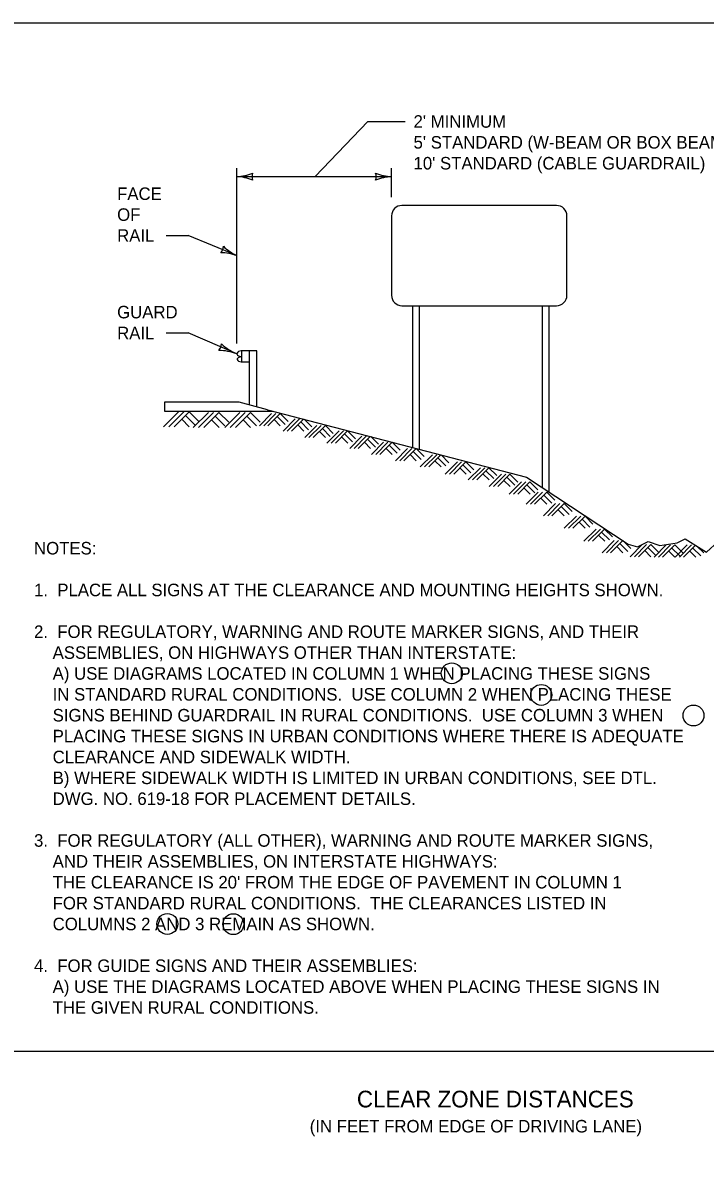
# Model space of a CAD drawing. Extents: x 49991.4 to 50021, y 49987.6 to 50011.4.
# Drawn here: x 50008.27 to 50011.54, y 49993.57 to 49999 of the extents above; entities that cross this region are included whole.
import ezdxf

# ---------------------------------------------------------------- set-up
doc = ezdxf.new("R2010")
doc.units = 0
for name, color, linetype in [('Level 1', 7, 'Continuous'), ('Level 2', 7, 'Continuous'), ('Level 3', 7, 'Continuous')]:
    doc.layers.add(name, color=color, linetype=linetype)

msp = doc.modelspace()

# ---------------------------------------------------------------- linework, layer by layer
at = {"layer": 'Level 1'}
for p, q in [((50010.8306, 49998.1235), (50010.0905, 49998.1235)), ((50010.0405, 49998.0735), (50010.0405, 49997.6934)), ((50010.8806, 49997.6934), (50010.8806, 49998.0735)), ((50010.0905, 49997.6434), (50010.8306, 49997.6434)), ((50010.1417, 49996.9646), (50010.1417, 49997.6434)), ((50010.1738, 49996.9562), (50010.1738, 49997.6434)), ((50010.7629, 49996.7725), (50010.7629, 49997.6434)), ((50010.795, 49996.7514), (50010.795, 49997.6434)), ((50009.3603, 49997.4275), (50009.3197, 49997.4275)), ((50009.3215, 49997.4275), (50009.3215, 49997.3742)), ((50009.3603, 49997.1675), (50009.3603, 49997.4275)), ((50009.3957, 49997.4275), (50009.3603, 49997.4275)), ((50009.3957, 49997.1586), (50009.3957, 49997.4275)), ((50009.3197, 49997.3742), (50009.3603, 49997.3742)), ((50008.9487, 49997.0636), (50009.0207, 49997.1356)), ((50009.31, 49997.1809), (50008.9538, 49997.1809)), ((50008.9538, 49997.1809), (50008.9538, 49997.1383)), ((50008.9538, 49997.1383), (50009.4739, 49997.1383)), ((50008.974, 49997.0636), (50009.046, 49997.1356)), ((50008.9991, 49997.0636), (50009.0711, 49997.1356)), ((50009.0711, 49997.1356), (50009.118, 49997.0888)), ((50009.0912, 49997.0606), (50009.1632, 49997.1326)), ((50009.1165, 49997.0606), (50009.1885, 49997.1326)), ((50009.1416, 49997.0606), (50009.2136, 49997.1326)), ((50009.2136, 49997.1326), (50009.2605, 49997.0858)), ((50009.2425, 49997.0606), (50009.3145, 49997.1326)), ((50009.2678, 49997.0606), (50009.3398, 49997.1326)), ((50009.2929, 49997.0606), (50009.3649, 49997.1326)), ((50009.446, 49997.1455), (50009.31, 49997.1809)), ((50009.3649, 49997.1326), (50009.4118, 49997.0858)), ((50009.446, 49997.1455), (50010.6864, 49996.8229)), ((50009.4737, 49997.1383), (50009.4737, 49997.1383)), ((50009.0355, 49997.0999), (50009.0719, 49997.0636)), ((50009.0534, 49997.1178), (50009.1002, 49997.0711)), ((50009.178, 49997.0969), (50009.2144, 49997.0606)), ((50009.1958, 49997.1148), (50009.2426, 49997.0681)), ((50009.3293, 49997.0969), (50009.3657, 49997.0606)), ((50009.3471, 49997.1148), (50009.3939, 49997.0681)), ((50009.4076, 49997.0684), (50009.4659, 49997.1267)), ((50009.4281, 49997.0684), (50009.4864, 49997.1267)), ((50009.4484, 49997.0684), (50009.5067, 49997.1267)), ((50009.4779, 49997.0979), (50009.5075, 49997.0684)), ((50009.4923, 49997.1124), (50009.5303, 49997.0745)), ((50009.5067, 49997.1267), (50009.5447, 49997.0888)), ((50009.5209, 49997.0431), (50009.5792, 49997.1014)), ((50009.5414, 49997.0431), (50009.5997, 49997.1014)), ((50009.5617, 49997.0431), (50009.6192, 49997.1005)), ((50009.6057, 49997.0871), (50009.6436, 49997.0492)), ((50009.6217, 49997.0998), (50009.658, 49997.0635)), ((50009.5912, 49997.0725), (50009.6208, 49997.0431)), ((50009.6246, 49997.0115), (50009.6829, 49997.0698)), ((50009.6451, 49997.0115), (50009.7034, 49997.0698)), ((50009.6654, 49997.0115), (50009.7237, 49997.0698)), ((50009.6949, 49997.041), (50009.7244, 49997.0115)), ((50009.7094, 49997.0555), (50009.7473, 49997.0176)), ((50009.7237, 49997.0698), (50009.7617, 49997.0319)), ((50009.731, 49996.9853), (50009.7893, 49997.0437)), ((50009.7516, 49996.9853), (50009.8099, 49997.0437)), ((50009.7719, 49996.9853), (50009.8302, 49997.0437)), ((50009.8158, 49997.0293), (50009.8537, 49996.9914)), ((50009.8302, 49997.0437), (50009.8682, 49997.0057)), ((50009.8014, 49997.0147), (50009.8309, 49996.9853)), ((50009.8405, 49996.9602), (50009.8988, 49997.0185)), ((50009.861, 49996.9602), (50009.9194, 49997.0185)), ((50009.8814, 49996.9602), (50009.9386, 49997.0174)), ((50009.9109, 49996.9896), (50009.9403, 49996.9602)), ((50009.9253, 49997.0041), (50009.9632, 49996.9664)), ((50009.9416, 49997.0166), (50009.9777, 49996.9807)), ((50009.944, 49996.9307), (50010.0023, 49996.9891)), ((50009.9646, 49996.9307), (50010.0229, 49996.9891)), ((50009.9848, 49996.9307), (50010.0431, 49996.9891)), ((50010.0287, 49996.9747), (50010.0667, 49996.9368)), ((50010.0431, 49996.9891), (50010.0812, 49996.9511)), ((50010.0143, 49996.9602), (50010.0438, 49996.9307)), ((50010.0589, 49996.9009), (50010.1172, 49996.9593)), ((50010.0795, 49996.9009), (50010.1378, 49996.9593)), ((50010.0997, 49996.9009), (50010.158, 49996.9593)), ((50010.1292, 49996.9304), (50010.1587, 49996.9009)), ((50010.1436, 49996.9449), (50010.1816, 49996.907)), ((50010.158, 49996.9593), (50010.1961, 49996.9213)), ((50010.1782, 49996.8711), (50010.2365, 49996.9295)), ((50010.1988, 49996.8711), (50010.2571, 49996.9295)), ((50010.219, 49996.8711), (50010.2771, 49996.9293)), ((50010.2629, 49996.9151), (50010.3009, 49996.8772)), ((50010.2776, 49996.9292), (50010.3154, 49996.8915)), ((50010.2485, 49996.9006), (50010.278, 49996.8711)), ((50010.2974, 49996.837), (50010.3557, 49996.8954)), ((50010.318, 49996.837), (50010.3763, 49996.8954)), ((50010.3382, 49996.837), (50010.3965, 49996.8954)), ((50010.3677, 49996.8665), (50010.3972, 49996.837)), ((50010.3821, 49996.881), (50010.4201, 49996.8431)), ((50010.3965, 49996.8954), (50010.4346, 49996.8574)), ((50010.4081, 49996.8093), (50010.4664, 49996.8677)), ((50010.4287, 49996.8093), (50010.487, 49996.8677)), ((50010.4489, 49996.8093), (50010.5072, 49996.8677)), ((50010.5072, 49996.8677), (50010.5453, 49996.8297)), ((50010.4784, 49996.8388), (50010.5079, 49996.8093)), ((50010.4928, 49996.8533), (50010.5308, 49996.8154)), ((50010.5082, 49996.7774), (50010.5665, 49996.8358)), ((50010.5288, 49996.7774), (50010.5871, 49996.8358)), ((50010.549, 49996.7774), (50010.6073, 49996.8358)), ((50010.5785, 49996.8069), (50010.608, 49996.7774)), ((50010.5929, 49996.8214), (50010.6309, 49996.7835)), ((50010.6073, 49996.8358), (50010.6454, 49996.7978)), ((50010.6864, 49996.8229), (50011.1739, 49996.5018)), ((50010.604, 49996.7412), (50010.6623, 49996.7996)), ((50010.6246, 49996.7412), (50010.6829, 49996.7996)), ((50010.6448, 49996.7412), (50010.7031, 49996.7996)), ((50010.6743, 49996.7707), (50010.7038, 49996.7412)), ((50010.6849, 49996.6922), (50010.7432, 49996.7506)), ((50010.6887, 49996.7852), (50010.7267, 49996.7473)), ((50010.7031, 49996.7996), (50010.7412, 49996.7616)), ((50010.7055, 49996.6922), (50010.7638, 49996.7506)), ((50010.7257, 49996.6922), (50010.784, 49996.7506)), ((50010.784, 49996.7506), (50010.8221, 49996.7126)), ((50010.7552, 49996.7217), (50010.7847, 49996.6922)), ((50010.768, 49996.6369), (50010.8263, 49996.6953)), ((50010.7696, 49996.7362), (50010.8076, 49996.6983)), ((50010.7886, 49996.6369), (50010.8469, 49996.6953)), ((50010.8088, 49996.6369), (50010.8671, 49996.6953)), ((50010.8671, 49996.6953), (50010.9052, 49996.6573)), ((50010.8383, 49996.6664), (50010.8678, 49996.6369)), ((50010.8527, 49996.6809), (50010.8907, 49996.643)), ((50010.868, 49996.5773), (50010.9263, 49996.6357)), ((50010.8886, 49996.5773), (50010.9469, 49996.6357)), ((50010.9088, 49996.5773), (50010.9671, 49996.6357)), ((50010.9383, 49996.6068), (50010.9678, 49996.5773)), ((50010.9527, 49996.6213), (50010.9907, 49996.5834)), ((50010.9671, 49996.6357), (50011.0052, 49996.5977)), ((50010.9617, 49996.5155), (50011.02, 49996.5739)), ((50010.9823, 49996.5155), (50011.0406, 49996.5739)), ((50011.0025, 49996.5155), (50011.0608, 49996.5739)), ((50011.032, 49996.545), (50011.0615, 49996.5155)), ((50011.0464, 49996.5595), (50011.0844, 49996.5216)), ((50011.0608, 49996.5739), (50011.0989, 49996.5359)), ((50011.0491, 49996.4601), (50011.1074, 49996.5185)), ((50011.0697, 49996.4601), (50011.128, 49996.5185)), ((50011.0899, 49996.4601), (50011.1482, 49996.5185)), ((50011.1194, 49996.4896), (50011.1489, 49996.4601)), ((50011.1338, 49996.5041), (50011.1718, 49996.4662)), ((50011.1482, 49996.5185), (50011.1863, 49996.4805)), ((50011.1831, 49996.441), (50011.2414, 49996.4994)), ((50011.2037, 49996.441), (50011.262, 49996.4994)), ((50011.2239, 49996.441), (50011.2822, 49996.4994)), ((50011.2678, 49996.485), (50011.3058, 49996.4471)), ((50011.2822, 49996.4994), (50011.3203, 49996.4614)), ((50011.2981, 49996.4389), (50011.3564, 49996.4973)), ((50011.3187, 49996.4389), (50011.377, 49996.4973)), ((50011.3389, 49996.4389), (50011.3972, 49996.4973)), ((50011.3828, 49996.4829), (50011.4208, 49996.445)), ((50011.3972, 49996.4973), (50011.4353, 49996.4593)), ((50011.3983, 49996.4389), (50011.4566, 49996.4973)), ((50011.4189, 49996.4389), (50011.4772, 49996.4973)), ((50011.4391, 49996.4389), (50011.4962, 49996.4961)), ((50011.483, 49996.4829), (50011.521, 49996.445)), ((50011.5025, 49996.4922), (50011.5355, 49996.4593)), ((50011.2534, 49996.4705), (50011.2829, 49996.441)), ((50011.3684, 49996.4684), (50011.3979, 49996.4389)), ((50011.4686, 49996.4684), (50011.4981, 49996.4389))]:
    msp.add_line(p, q, dxfattribs=at)
msp.add_lwpolyline([(49999.3835, 49998.9992), (50016.7501, 49998.9992), (50016.7501, 49987.7988), (49999.3835, 49987.7988)], close=True, dxfattribs=at)
msp.add_lwpolyline([(50011.1739, 49996.5018), (50011.2183, 49996.4891), (50011.2691, 49996.5144), (50011.3261, 49996.4954), (50011.4086, 49996.5081), (50011.4467, 49996.5271), (50011.5481, 49996.4637), (50011.6052, 49996.5144), (50011.6876, 49996.5081), (50011.7131, 49996.5017)], dxfattribs=at)
for centre, start, end in [((50010.0905, 49998.0735), 90, 180), ((50010.8305, 49998.0735), 0, 90), ((50010.0904, 49997.6934), 180, 270), ((50010.8305, 49997.6935), 270, 0)]:
    msp.add_arc(centre, 0.05, start, end, dxfattribs=at)
msp.add_spline([(50009.3197, 49997.4275), (50009.301, 49997.4169), (50009.3006, 49997.4099), (50009.3197, 49997.4008), (50009.3204, 49997.4006), (50009.3006, 49997.3894), (50009.301, 49997.3857), (50009.3197, 49997.3742)], degree=3, dxfattribs=at)
at = {"layer": 'Level 2'}
for centre in [(50010.329, 49995.8827), (50010.7574, 49995.7791), (50011.4867, 49995.6807), (50008.9668, 49994.682), (50009.2827, 49994.6811)]:
    msp.add_circle(centre, 0.0501, dxfattribs=at)
at = {"layer": 'Level 3'}
for p, q in [((50009.9272, 49998.526), (50009.6752, 49998.2617)), ((50009.9272, 49998.526), (50010.1059, 49998.526)), ((50009.2993, 49997.462), (50009.2993, 49998.3017)), ((50010.0405, 49998.1635), (50010.0405, 49998.3017)), ((50009.2993, 49998.2617), (50010.0405, 49998.2617)), ((50008.9614, 49997.9799), (50009.0669, 49997.9799)), ((50009.2993, 49997.8836), (50009.0669, 49997.9799)), ((50008.9614, 49997.5128), (50009.0669, 49997.5128)), ((50009.2993, 49997.4134), (50009.0669, 49997.5128)), ((50008.0668, 49994.0732), (50016.7501, 49994.0732))]:
    msp.add_line(p, q, dxfattribs=at)
for centre, radius, start, end in [((50009.2878, 49998.4944), 0.233, 272.8273, 292.0772), ((50009.4275, 49998.2617), 0.0548, 162.1388, 197.8612), ((50010.0497, 49998.4838), 0.2223, 247.456, 267.6395), ((50009.9123, 49998.2617), 0.0548, 342.1388, 17.8612), ((50009.2901, 49998.0396), 0.2223, 67.456, 87.6395), ((50010.052, 49998.029), 0.233, 92.8273, 112.0772), ((50009.1807, 49997.9323), 0.0548, 319.831, 355.5533), ((50009.2216, 49997.6639), 0.233, 70.5194, 89.7693), ((50009.3921, 49998.0856), 0.2223, 225.1481, 245.3317)]:
    msp.add_arc(centre, radius, start, end, dxfattribs=at)
for centre, major_axis, start_param, end_param in [((50009.1647, 49997.4668), (0.0575, -0.0228), 5.971325, 6.594798), ((50009.3907, 49997.6161), (-0.2335, 0.0924), 1.177206, 1.529474), ((50009.2257, 49997.1923), (-0.2447, 0.0969), 4.761611, 5.097584)]:
    msp.add_ellipse(centre, major_axis=major_axis, ratio=0.885405, start_param=start_param, end_param=end_param, dxfattribs=at)

# ---------------------------------------------------------------- texts
at = {"layer": 'Level 2'}
for s, height, p in [("2' MINIMUM", 0.06, (50010.1459, 49998.496)), ("5' STANDARD (W-BEAM OR BOX BEAM GUARDRAIL)", 0.06, (50010.1459, 49998.396)), ("10' STANDARD (CABLE GUARDRAIL) ", 0.06, (50010.1459, 49998.296)), ('FACE', 0.06, (50008.7263, 49998.1499)), ('OF', 0.06, (50008.7263, 49998.0499)), ('RAIL', 0.06, (50008.7263, 49997.9499)), ('GUARD', 0.06, (50008.7263, 49997.5828)), ('RAIL', 0.06, (50008.7263, 49997.4828)), ('NOTES:', 0.06, (50008.3284, 49996.452)), ('1.  PLACE ALL SIGNS AT THE CLEARANCE AND MOUNTING HEIGHTS SHOWN.', 0.06, (50008.3284, 49996.252)), ('2.  FOR REGULATORY, WARNING AND ROUTE MARKER SIGNS, AND THEIR', 0.06, (50008.3284, 49996.052)), ('    ASSEMBLIES, ON HIGHWAYS OTHER THAN INTERSTATE:', 0.06, (50008.3284, 49995.952)), ('    A) USE DIAGRAMS LOCATED IN COLUMN 1 WHEN PLACING THESE SIGNS', 0.06, (50008.3284, 49995.852)), ('    IN STANDARD RURAL CONDITIONS.  USE COLUMN 2 WHEN PLACING THESE', 0.06, (50008.3284, 49995.752)), ('    SIGNS BEHIND GUARDRAIL IN RURAL CONDITIONS.  USE COLUMN 3 WHEN', 0.06, (50008.3284, 49995.652)), ('    PLACING THESE SIGNS IN URBAN CONDITIONS WHERE THERE IS ADEQUATE', 0.06, (50008.3284, 49995.552)), ('    CLEARANCE AND SIDEWALK WIDTH.', 0.06, (50008.3284, 49995.452)), ('    B) WHERE SIDEWALK WIDTH IS LIMITED IN URBAN CONDITIONS, SEE DTL.', 0.06, (50008.3284, 49995.352)), ('    DWG. NO. 619-18 FOR PLACEMENT DETAILS.', 0.06, (50008.3284, 49995.252)), ('3.  FOR REGULATORY (ALL OTHER), WARNING AND ROUTE MARKER SIGNS,', 0.06, (50008.3284, 49995.052)), ('    AND THEIR ASSEMBLIES, ON INTERSTATE HIGHWAYS:', 0.06, (50008.3284, 49994.952)), ("    THE CLEARANCE IS 20' FROM THE EDGE OF PAVEMENT IN COLUMN 1", 0.06, (50008.3284, 49994.852)), ('    FOR STANDARD RURAL CONDITIONS.  THE CLEARANCES LISTED IN', 0.06, (50008.3284, 49994.752)), ('    COLUMNS 2 AND 3 REMAIN AS SHOWN.', 0.06, (50008.3284, 49994.652)), ('4.  FOR GUIDE SIGNS AND THEIR ASSEMBLIES:', 0.06, (50008.3284, 49994.452)), ('    A) USE THE DIAGRAMS LOCATED ABOVE WHEN PLACING THESE SIGNS IN', 0.06, (50008.3284, 49994.352)), ('    THE GIVEN RURAL CONDITIONS.    ', 0.06, (50008.3284, 49994.252)), ('CLEAR ZONE DISTANCES', 0.08, (50009.8746, 49993.8033)), ('(IN FEET FROM EDGE OF DRIVING LANE)', 0.06, (50009.6487, 49993.6833))]:
    msp.add_text(s, height=height, dxfattribs=at).set_placement(p)

doc.saveas('drawing.dxf')
